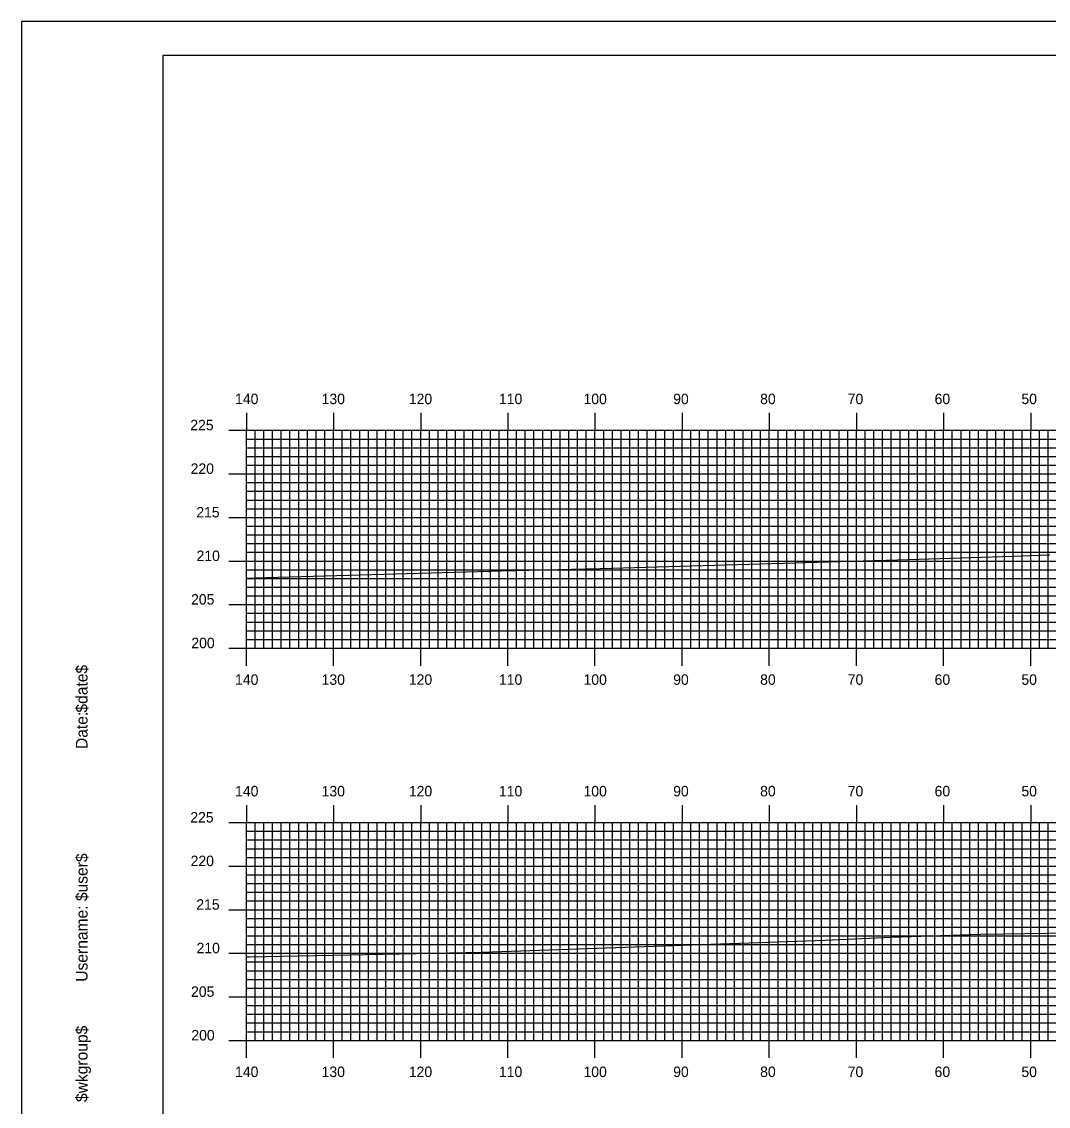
# Model space of a CAD drawing. Extents: x 1821211 to 1821555, y 442591 to 442811.
# Drawn here: x 1821211.4 to 1821329.2, y 442686.1 to 442810.5 of the extents above; entities that cross this region are included whole.
import ezdxf

# ---------------------------------------------------------------- set-up
doc = ezdxf.new("R2010")
doc.units = 0
for name, color, linetype in [('BORDER', 7, 'Continuous'), ('H_V ANNOTATION', 7, 'Continuous'), ('MAJOR', 7, 'Continuous'), ('MINOR', 7, 'Continuous'), ('PLOT BOUNDARY', 7, 'Continuous'), ('S_Roadway_Centerline', 7, 'Continuous')]:
    doc.layers.add(name, color=color, linetype=linetype)

msp = doc.modelspace()

# ---------------------------------------------------------------- linework, layer by layer
at = {"layer": 'BORDER'}
msp.add_lwpolyline([(1821227.63, 442596.67), (1821547.63, 442596.67), (1821547.63, 442806.67), (1821227.63, 442806.67)], close=True, dxfattribs=at)
at = {"layer": 'MAJOR'}
for p, q in [((1821237.23, 442765.67), (1821237.23, 442763.67)), ((1821247.23, 442765.67), (1821247.23, 442763.67)), ((1821257.23, 442765.67), (1821257.23, 442763.67)), ((1821267.23, 442765.67), (1821267.23, 442763.67)), ((1821277.23, 442765.67), (1821277.23, 442763.67)), ((1821287.23, 442765.67), (1821287.23, 442763.67)), ((1821297.23, 442765.67), (1821297.23, 442763.67)), ((1821307.23, 442765.67), (1821307.23, 442763.67)), ((1821317.23, 442765.67), (1821317.23, 442763.67)), ((1821327.23, 442765.67), (1821327.23, 442763.67)), ((1821235.23, 442763.67), (1821237.23, 442763.67)), ((1821237.23, 442763.67), (1821517.23, 442763.67)), ((1821237.23, 442738.67), (1821237.23, 442763.67)), ((1821237.23, 442738.67), (1821237.23, 442763.67)), ((1821237.23, 442763.67), (1821517.23, 442763.67)), ((1821247.23, 442738.67), (1821247.23, 442763.67)), ((1821257.23, 442738.67), (1821257.23, 442763.67)), ((1821267.23, 442738.67), (1821267.23, 442763.67)), ((1821277.23, 442738.67), (1821277.23, 442763.67)), ((1821287.23, 442738.67), (1821287.23, 442763.67)), ((1821297.23, 442738.67), (1821297.23, 442763.67)), ((1821307.23, 442738.67), (1821307.23, 442763.67)), ((1821317.23, 442738.67), (1821317.23, 442763.67)), ((1821327.23, 442738.67), (1821327.23, 442763.67)), ((1821235.23, 442758.67), (1821237.23, 442758.67)), ((1821237.23, 442758.67), (1821517.23, 442758.67)), ((1821235.23, 442753.67), (1821237.23, 442753.67)), ((1821237.23, 442753.67), (1821517.23, 442753.67)), ((1821235.23, 442748.67), (1821237.23, 442748.67)), ((1821237.23, 442748.67), (1821517.23, 442748.67)), ((1821235.23, 442743.67), (1821237.23, 442743.67)), ((1821237.23, 442743.67), (1821517.23, 442743.67)), ((1821235.23, 442738.67), (1821237.23, 442738.67)), ((1821237.23, 442738.67), (1821517.23, 442738.67)), ((1821237.23, 442738.67), (1821517.23, 442738.67)), ((1821237.23, 442736.66), (1821237.23, 442738.67)), ((1821247.23, 442736.66), (1821247.23, 442738.67)), ((1821257.23, 442736.66), (1821257.23, 442738.67)), ((1821267.23, 442736.66), (1821267.23, 442738.67)), ((1821277.23, 442736.66), (1821277.23, 442738.67)), ((1821287.23, 442736.66), (1821287.23, 442738.67)), ((1821297.23, 442736.66), (1821297.23, 442738.67)), ((1821307.23, 442736.66), (1821307.23, 442738.67)), ((1821317.23, 442736.66), (1821317.23, 442738.67)), ((1821327.23, 442736.66), (1821327.23, 442738.67)), ((1821237.23, 442720.67), (1821237.23, 442718.67)), ((1821247.23, 442720.67), (1821247.23, 442718.67)), ((1821257.23, 442720.67), (1821257.23, 442718.67)), ((1821267.23, 442720.67), (1821267.23, 442718.67)), ((1821277.23, 442720.67), (1821277.23, 442718.67)), ((1821287.23, 442720.67), (1821287.23, 442718.67)), ((1821297.23, 442720.67), (1821297.23, 442718.67)), ((1821307.23, 442720.67), (1821307.23, 442718.67)), ((1821317.23, 442720.67), (1821317.23, 442718.67)), ((1821327.23, 442720.67), (1821327.23, 442718.67)), ((1821235.23, 442718.67), (1821237.23, 442718.67)), ((1821237.23, 442718.67), (1821517.23, 442718.67)), ((1821237.23, 442693.67), (1821237.23, 442718.67)), ((1821237.23, 442693.67), (1821237.23, 442718.67)), ((1821237.23, 442718.67), (1821517.23, 442718.67)), ((1821247.23, 442693.67), (1821247.23, 442718.67)), ((1821257.23, 442693.67), (1821257.23, 442718.67)), ((1821267.23, 442693.67), (1821267.23, 442718.67)), ((1821277.23, 442693.67), (1821277.23, 442718.67)), ((1821287.23, 442693.67), (1821287.23, 442718.67)), ((1821297.23, 442693.67), (1821297.23, 442718.67)), ((1821307.23, 442693.67), (1821307.23, 442718.67)), ((1821317.23, 442693.67), (1821317.23, 442718.67)), ((1821327.23, 442693.67), (1821327.23, 442718.67)), ((1821235.23, 442713.67), (1821237.23, 442713.67)), ((1821237.23, 442713.67), (1821517.23, 442713.67)), ((1821235.23, 442708.67), (1821237.23, 442708.67)), ((1821237.23, 442708.67), (1821517.23, 442708.67)), ((1821235.23, 442703.67), (1821237.23, 442703.67)), ((1821237.23, 442703.67), (1821517.23, 442703.67)), ((1821235.23, 442698.67), (1821237.23, 442698.67)), ((1821237.23, 442698.67), (1821517.23, 442698.67)), ((1821235.23, 442693.67), (1821237.23, 442693.67)), ((1821237.23, 442693.67), (1821517.23, 442693.67)), ((1821237.23, 442693.67), (1821517.23, 442693.67)), ((1821237.23, 442691.66), (1821237.23, 442693.67)), ((1821247.23, 442691.66), (1821247.23, 442693.67)), ((1821257.23, 442691.66), (1821257.23, 442693.67)), ((1821267.23, 442691.66), (1821267.23, 442693.67)), ((1821277.23, 442691.66), (1821277.23, 442693.67)), ((1821287.23, 442691.66), (1821287.23, 442693.67)), ((1821297.23, 442691.66), (1821297.23, 442693.67)), ((1821307.23, 442691.66), (1821307.23, 442693.67)), ((1821317.23, 442691.66), (1821317.23, 442693.67)), ((1821327.23, 442691.66), (1821327.23, 442693.67))]:
    msp.add_line(p, q, dxfattribs=at)
at = {"layer": 'MINOR'}
for p, q in [((1821237.23, 442762.67), (1821517.23, 442762.67)), ((1821237.23, 442762.67), (1821239.23, 442762.67)), ((1821238.23, 442738.67), (1821238.23, 442763.67)), ((1821239.23, 442738.67), (1821239.23, 442763.67)), ((1821240.23, 442738.67), (1821240.23, 442763.67)), ((1821241.23, 442738.67), (1821241.23, 442763.67)), ((1821242.23, 442738.67), (1821242.23, 442763.67)), ((1821243.23, 442738.67), (1821243.23, 442763.67)), ((1821244.23, 442738.67), (1821244.23, 442763.67)), ((1821245.23, 442738.67), (1821245.23, 442763.67)), ((1821246.23, 442738.67), (1821246.23, 442763.67)), ((1821248.23, 442738.67), (1821248.23, 442763.67)), ((1821249.23, 442738.67), (1821249.23, 442763.67)), ((1821250.23, 442738.67), (1821250.23, 442763.67)), ((1821251.23, 442738.67), (1821251.23, 442763.67)), ((1821252.23, 442738.67), (1821252.23, 442763.67)), ((1821253.23, 442738.67), (1821253.23, 442763.67)), ((1821254.23, 442738.67), (1821254.23, 442763.67)), ((1821255.23, 442738.67), (1821255.23, 442763.67)), ((1821256.23, 442738.67), (1821256.23, 442763.67)), ((1821258.23, 442738.67), (1821258.23, 442763.67)), ((1821259.23, 442738.67), (1821259.23, 442763.67)), ((1821260.23, 442738.67), (1821260.23, 442763.67)), ((1821261.23, 442738.67), (1821261.23, 442763.67)), ((1821262.23, 442738.67), (1821262.23, 442763.67)), ((1821263.23, 442738.67), (1821263.23, 442763.67)), ((1821264.23, 442738.67), (1821264.23, 442763.67)), ((1821265.23, 442738.67), (1821265.23, 442763.67)), ((1821266.23, 442738.67), (1821266.23, 442763.67)), ((1821268.23, 442738.67), (1821268.23, 442763.67)), ((1821269.23, 442738.67), (1821269.23, 442763.67)), ((1821270.23, 442738.67), (1821270.23, 442763.67)), ((1821271.23, 442738.67), (1821271.23, 442763.67)), ((1821272.23, 442738.67), (1821272.23, 442763.67)), ((1821273.23, 442738.67), (1821273.23, 442763.67)), ((1821274.23, 442738.67), (1821274.23, 442763.67)), ((1821275.23, 442738.67), (1821275.23, 442763.67)), ((1821276.23, 442738.67), (1821276.23, 442763.67)), ((1821278.23, 442738.67), (1821278.23, 442763.67)), ((1821279.23, 442738.67), (1821279.23, 442763.67)), ((1821280.23, 442738.67), (1821280.23, 442763.67)), ((1821281.23, 442738.67), (1821281.23, 442763.67)), ((1821282.23, 442738.67), (1821282.23, 442763.67)), ((1821283.23, 442738.67), (1821283.23, 442763.67)), ((1821284.23, 442738.67), (1821284.23, 442763.67)), ((1821285.23, 442738.67), (1821285.23, 442763.67)), ((1821286.23, 442738.67), (1821286.23, 442763.67)), ((1821288.23, 442738.67), (1821288.23, 442763.67)), ((1821289.23, 442738.67), (1821289.23, 442763.67)), ((1821290.23, 442738.67), (1821290.23, 442763.67)), ((1821291.23, 442738.67), (1821291.23, 442763.67)), ((1821292.23, 442738.67), (1821292.23, 442763.67)), ((1821293.23, 442738.67), (1821293.23, 442763.67)), ((1821294.23, 442738.67), (1821294.23, 442763.67)), ((1821295.23, 442738.67), (1821295.23, 442763.67)), ((1821296.23, 442738.67), (1821296.23, 442763.67)), ((1821298.23, 442738.67), (1821298.23, 442763.67)), ((1821299.23, 442738.67), (1821299.23, 442763.67)), ((1821300.23, 442738.67), (1821300.23, 442763.67)), ((1821301.23, 442738.67), (1821301.23, 442763.67)), ((1821302.23, 442738.67), (1821302.23, 442763.67)), ((1821303.23, 442738.67), (1821303.23, 442763.67)), ((1821304.23, 442738.67), (1821304.23, 442763.67)), ((1821305.23, 442738.67), (1821305.23, 442763.67)), ((1821306.23, 442738.67), (1821306.23, 442763.67)), ((1821308.23, 442738.67), (1821308.23, 442763.67)), ((1821309.23, 442738.67), (1821309.23, 442763.67)), ((1821310.23, 442738.67), (1821310.23, 442763.67)), ((1821311.23, 442738.67), (1821311.23, 442763.67)), ((1821312.23, 442738.67), (1821312.23, 442763.67)), ((1821313.23, 442738.67), (1821313.23, 442763.67)), ((1821314.23, 442738.67), (1821314.23, 442763.67)), ((1821315.23, 442738.67), (1821315.23, 442763.67)), ((1821316.23, 442738.67), (1821316.23, 442763.67)), ((1821318.23, 442738.67), (1821318.23, 442763.67)), ((1821319.23, 442738.67), (1821319.23, 442763.67)), ((1821320.23, 442738.67), (1821320.23, 442763.67)), ((1821321.23, 442738.67), (1821321.23, 442763.67)), ((1821322.23, 442738.67), (1821322.23, 442763.67)), ((1821323.23, 442738.67), (1821323.23, 442763.67)), ((1821324.23, 442738.67), (1821324.23, 442763.67)), ((1821325.23, 442738.67), (1821325.23, 442763.67)), ((1821326.23, 442738.67), (1821326.23, 442763.67)), ((1821328.23, 442738.67), (1821328.23, 442763.67)), ((1821329.23, 442738.67), (1821329.23, 442763.67)), ((1821237.23, 442761.67), (1821517.23, 442761.67)), ((1821237.23, 442761.67), (1821239.23, 442761.67)), ((1821237.23, 442760.67), (1821517.23, 442760.67)), ((1821237.23, 442760.67), (1821239.23, 442760.67)), ((1821237.23, 442759.67), (1821517.23, 442759.67)), ((1821237.23, 442759.67), (1821239.23, 442759.67)), ((1821237.23, 442757.67), (1821517.23, 442757.67)), ((1821237.23, 442757.67), (1821239.23, 442757.67)), ((1821237.23, 442756.67), (1821517.23, 442756.67)), ((1821237.23, 442756.67), (1821239.23, 442756.67)), ((1821237.23, 442755.67), (1821517.23, 442755.67)), ((1821237.23, 442755.67), (1821239.23, 442755.67)), ((1821237.23, 442754.67), (1821517.23, 442754.67)), ((1821237.23, 442754.67), (1821239.23, 442754.67)), ((1821237.23, 442752.67), (1821517.23, 442752.67)), ((1821237.23, 442752.67), (1821239.23, 442752.67)), ((1821237.23, 442751.67), (1821517.23, 442751.67)), ((1821237.23, 442751.67), (1821239.23, 442751.67)), ((1821237.23, 442750.67), (1821517.23, 442750.67)), ((1821237.23, 442750.67), (1821239.23, 442750.67)), ((1821237.23, 442749.67), (1821517.23, 442749.67)), ((1821237.23, 442749.67), (1821239.23, 442749.67)), ((1821237.23, 442747.67), (1821517.23, 442747.67)), ((1821237.23, 442747.67), (1821239.23, 442747.67)), ((1821237.23, 442746.67), (1821517.23, 442746.67)), ((1821237.23, 442746.67), (1821239.23, 442746.67)), ((1821237.23, 442745.67), (1821517.23, 442745.67)), ((1821237.23, 442745.67), (1821239.23, 442745.67)), ((1821237.23, 442744.67), (1821517.23, 442744.67)), ((1821237.23, 442744.67), (1821239.23, 442744.67)), ((1821237.23, 442742.67), (1821517.23, 442742.67)), ((1821237.23, 442742.67), (1821239.23, 442742.67)), ((1821237.23, 442741.67), (1821517.23, 442741.67)), ((1821237.23, 442741.67), (1821239.23, 442741.67)), ((1821237.23, 442740.67), (1821517.23, 442740.67)), ((1821237.23, 442740.67), (1821239.23, 442740.67)), ((1821237.23, 442739.67), (1821517.23, 442739.67)), ((1821237.23, 442739.67), (1821239.23, 442739.67)), ((1821238.23, 442693.67), (1821238.23, 442718.67)), ((1821239.23, 442693.67), (1821239.23, 442718.67)), ((1821240.23, 442693.67), (1821240.23, 442718.67)), ((1821241.23, 442693.67), (1821241.23, 442718.67)), ((1821242.23, 442693.67), (1821242.23, 442718.67)), ((1821243.23, 442693.67), (1821243.23, 442718.67)), ((1821244.23, 442693.67), (1821244.23, 442718.67)), ((1821245.23, 442693.67), (1821245.23, 442718.67)), ((1821246.23, 442693.67), (1821246.23, 442718.67)), ((1821248.23, 442693.67), (1821248.23, 442718.67)), ((1821249.23, 442693.67), (1821249.23, 442718.67)), ((1821250.23, 442693.67), (1821250.23, 442718.67)), ((1821251.23, 442693.67), (1821251.23, 442718.67)), ((1821252.23, 442693.67), (1821252.23, 442718.67)), ((1821253.23, 442693.67), (1821253.23, 442718.67)), ((1821254.23, 442693.67), (1821254.23, 442718.67)), ((1821255.23, 442693.67), (1821255.23, 442718.67)), ((1821256.23, 442693.67), (1821256.23, 442718.67)), ((1821258.23, 442693.67), (1821258.23, 442718.67)), ((1821259.23, 442693.67), (1821259.23, 442718.67)), ((1821260.23, 442693.67), (1821260.23, 442718.67)), ((1821261.23, 442693.67), (1821261.23, 442718.67)), ((1821262.23, 442693.67), (1821262.23, 442718.67)), ((1821263.23, 442693.67), (1821263.23, 442718.67)), ((1821264.23, 442693.67), (1821264.23, 442718.67)), ((1821265.23, 442693.67), (1821265.23, 442718.67)), ((1821266.23, 442693.67), (1821266.23, 442718.67)), ((1821268.23, 442693.67), (1821268.23, 442718.67)), ((1821269.23, 442693.67), (1821269.23, 442718.67)), ((1821270.23, 442693.67), (1821270.23, 442718.67)), ((1821271.23, 442693.67), (1821271.23, 442718.67)), ((1821272.23, 442693.67), (1821272.23, 442718.67)), ((1821273.23, 442693.67), (1821273.23, 442718.67)), ((1821274.23, 442693.67), (1821274.23, 442718.67)), ((1821275.23, 442693.67), (1821275.23, 442718.67)), ((1821276.23, 442693.67), (1821276.23, 442718.67)), ((1821278.23, 442693.67), (1821278.23, 442718.67)), ((1821279.23, 442693.67), (1821279.23, 442718.67)), ((1821280.23, 442693.67), (1821280.23, 442718.67)), ((1821281.23, 442693.67), (1821281.23, 442718.67)), ((1821282.23, 442693.67), (1821282.23, 442718.67)), ((1821283.23, 442693.67), (1821283.23, 442718.67)), ((1821284.23, 442693.67), (1821284.23, 442718.67)), ((1821285.23, 442693.67), (1821285.23, 442718.67)), ((1821286.23, 442693.67), (1821286.23, 442718.67)), ((1821288.23, 442693.67), (1821288.23, 442718.67)), ((1821289.23, 442693.67), (1821289.23, 442718.67)), ((1821290.23, 442693.67), (1821290.23, 442718.67)), ((1821291.23, 442693.67), (1821291.23, 442718.67)), ((1821292.23, 442693.67), (1821292.23, 442718.67)), ((1821293.23, 442693.67), (1821293.23, 442718.67)), ((1821294.23, 442693.67), (1821294.23, 442718.67)), ((1821295.23, 442693.67), (1821295.23, 442718.67)), ((1821296.23, 442693.67), (1821296.23, 442718.67)), ((1821298.23, 442693.67), (1821298.23, 442718.67)), ((1821299.23, 442693.67), (1821299.23, 442718.67)), ((1821300.23, 442693.67), (1821300.23, 442718.67)), ((1821301.23, 442693.67), (1821301.23, 442718.67)), ((1821302.23, 442693.67), (1821302.23, 442718.67)), ((1821303.23, 442693.67), (1821303.23, 442718.67)), ((1821304.23, 442693.67), (1821304.23, 442718.67)), ((1821305.23, 442693.67), (1821305.23, 442718.67)), ((1821306.23, 442693.67), (1821306.23, 442718.67)), ((1821308.23, 442693.67), (1821308.23, 442718.67)), ((1821309.23, 442693.67), (1821309.23, 442718.67)), ((1821310.23, 442693.67), (1821310.23, 442718.67)), ((1821311.23, 442693.67), (1821311.23, 442718.67)), ((1821312.23, 442693.67), (1821312.23, 442718.67)), ((1821313.23, 442693.67), (1821313.23, 442718.67)), ((1821314.23, 442693.67), (1821314.23, 442718.67)), ((1821315.23, 442693.67), (1821315.23, 442718.67)), ((1821316.23, 442693.67), (1821316.23, 442718.67)), ((1821318.23, 442693.67), (1821318.23, 442718.67)), ((1821319.23, 442693.67), (1821319.23, 442718.67)), ((1821320.23, 442693.67), (1821320.23, 442718.67)), ((1821321.23, 442693.67), (1821321.23, 442718.67)), ((1821322.23, 442693.67), (1821322.23, 442718.67)), ((1821323.23, 442693.67), (1821323.23, 442718.67)), ((1821324.23, 442693.67), (1821324.23, 442718.67)), ((1821325.23, 442693.67), (1821325.23, 442718.67)), ((1821326.23, 442693.67), (1821326.23, 442718.67)), ((1821328.23, 442693.67), (1821328.23, 442718.67)), ((1821329.23, 442693.67), (1821329.23, 442718.67)), ((1821237.23, 442717.67), (1821517.23, 442717.67)), ((1821237.23, 442717.67), (1821239.23, 442717.67)), ((1821237.23, 442716.67), (1821517.23, 442716.67)), ((1821237.23, 442716.67), (1821239.23, 442716.67)), ((1821237.23, 442715.67), (1821517.23, 442715.67)), ((1821237.23, 442715.67), (1821239.23, 442715.67)), ((1821237.23, 442714.67), (1821517.23, 442714.67)), ((1821237.23, 442714.67), (1821239.23, 442714.67)), ((1821237.23, 442712.67), (1821517.23, 442712.67)), ((1821237.23, 442712.67), (1821239.23, 442712.67)), ((1821237.23, 442711.67), (1821517.23, 442711.67)), ((1821237.23, 442711.67), (1821239.23, 442711.67)), ((1821237.23, 442710.67), (1821517.23, 442710.67)), ((1821237.23, 442710.67), (1821239.23, 442710.67)), ((1821237.23, 442709.67), (1821517.23, 442709.67)), ((1821237.23, 442709.67), (1821239.23, 442709.67)), ((1821237.23, 442707.67), (1821517.23, 442707.67)), ((1821237.23, 442707.67), (1821239.23, 442707.67)), ((1821237.23, 442706.67), (1821517.23, 442706.67)), ((1821237.23, 442706.67), (1821239.23, 442706.67)), ((1821237.23, 442705.67), (1821517.23, 442705.67)), ((1821237.23, 442705.67), (1821239.23, 442705.67)), ((1821237.23, 442704.67), (1821517.23, 442704.67)), ((1821237.23, 442704.67), (1821239.23, 442704.67)), ((1821237.23, 442702.67), (1821517.23, 442702.67)), ((1821237.23, 442702.67), (1821239.23, 442702.67)), ((1821237.23, 442701.67), (1821517.23, 442701.67)), ((1821237.23, 442701.67), (1821239.23, 442701.67)), ((1821237.23, 442700.67), (1821517.23, 442700.67)), ((1821237.23, 442700.67), (1821239.23, 442700.67)), ((1821237.23, 442699.67), (1821517.23, 442699.67)), ((1821237.23, 442699.67), (1821239.23, 442699.67)), ((1821237.23, 442697.67), (1821517.23, 442697.67)), ((1821237.23, 442697.67), (1821239.23, 442697.67)), ((1821237.23, 442696.67), (1821517.23, 442696.67)), ((1821237.23, 442696.67), (1821239.23, 442696.67)), ((1821237.23, 442695.67), (1821517.23, 442695.67)), ((1821237.23, 442695.67), (1821239.23, 442695.67)), ((1821237.23, 442694.67), (1821517.23, 442694.67)), ((1821237.23, 442694.67), (1821239.23, 442694.67))]:
    msp.add_line(p, q, dxfattribs=at)
at = {"layer": 'PLOT BOUNDARY'}
msp.add_lwpolyline([(1821211.44, 442590.55), (1821551.44, 442590.55), (1821551.44, 442810.55), (1821211.44, 442810.55)], close=True, dxfattribs=at)
at = {"layer": 'S_Roadway_Centerline'}
for points in [[(1821237.23, 442746.71), (1821238.14, 442746.75), (1821266.46, 442747.53), (1821274.53, 442747.74), (1821277.82, 442747.81), (1821313.25, 442748.83), (1821325.17, 442749.23), (1821329.44, 442749.38)], [(1821237.23, 442703.27), (1821237.53, 442703.28), (1821264.33, 442703.79), (1821303.65, 442705.19), (1821311.23, 442705.53), (1821321.49, 442705.86), (1821351.91, 442706.32), (1821353.94, 442706.35), (1821354.59, 442706.37), (1821355.88, 442706.42), (1821388.83, 442707.87), (1821420.29, 442709.25), (1821422.31, 442709.32), (1821426.24, 442709.4), (1821439.35, 442709.51), (1821465.23, 442709.52), (1821471.24, 442709.51), (1821476.19, 442709.63), (1821481.91, 442709.95), (1821490.45, 442710.34), (1821494.15, 442710.38), (1821514.65, 442710.89), (1821517.23, 442710.91)]]:
    msp.add_lwpolyline(points, dxfattribs=at)

# ---------------------------------------------------------------- texts
at = {"layer": 'BORDER'}
for s, p in [('$date$', (1821219, 442731.28)), ('Date:', (1821219, 442727.1)), ('$user$', (1821219, 442709.65)), ('Username:', (1821219, 442700.4)), ('$wkgroup$', (1821219, 442686.6))]:
    msp.add_text(s, height=1.339, rotation=90, dxfattribs=at).set_placement(p)
at = {"layer": 'H_V ANNOTATION'}
for s, p in [('140', (1821235.93, 442766.67)), ('130', (1821245.86, 442766.67)), ('120', (1821255.87, 442766.67)), ('110', (1821266.21, 442766.67)), ('100', (1821275.91, 442766.67)), ('90', (1821286.2, 442766.67)), ('80', (1821296.18, 442766.67)), ('70', (1821306.23, 442766.67)), ('60', (1821316.2, 442766.67)), ('50', (1821326.16, 442766.67)), ('225', (1821230.79, 442763.67)), ('220', (1821230.83, 442758.67)), ('215', (1821231.48, 442753.67)), ('210', (1821231.51, 442748.67)), ('205', (1821230.88, 442743.67)), ('200', (1821230.91, 442738.67)), ('140', (1821235.93, 442734.47)), ('130', (1821245.86, 442734.47)), ('120', (1821255.87, 442734.47)), ('110', (1821266.21, 442734.47)), ('100', (1821275.91, 442734.47)), ('90', (1821286.2, 442734.47)), ('80', (1821296.18, 442734.47)), ('70', (1821306.23, 442734.47)), ('60', (1821316.2, 442734.47)), ('50', (1821326.16, 442734.47)), ('140', (1821235.93, 442721.67)), ('130', (1821245.86, 442721.67)), ('120', (1821255.87, 442721.67)), ('110', (1821266.21, 442721.67)), ('100', (1821275.91, 442721.67)), ('90', (1821286.2, 442721.67)), ('80', (1821296.18, 442721.67)), ('70', (1821306.23, 442721.67)), ('60', (1821316.2, 442721.67)), ('50', (1821326.16, 442721.67)), ('225', (1821230.79, 442718.67)), ('220', (1821230.83, 442713.67)), ('215', (1821231.48, 442708.67)), ('210', (1821231.51, 442703.67)), ('205', (1821230.88, 442698.67)), ('200', (1821230.91, 442693.67)), ('140', (1821235.93, 442689.47)), ('130', (1821245.86, 442689.47)), ('120', (1821255.87, 442689.47)), ('110', (1821266.21, 442689.47)), ('100', (1821275.91, 442689.47)), ('90', (1821286.2, 442689.47)), ('80', (1821296.18, 442689.47)), ('70', (1821306.23, 442689.47)), ('60', (1821316.2, 442689.47)), ('50', (1821326.16, 442689.47))]:
    msp.add_text(s, height=1.2, dxfattribs=at).set_placement(p)
at = {"layer": 'MAJOR'}
for p in [(1821237.22, 442738.67), (1821237.22, 442693.67)]:
    msp.add_text('-', height=0.012, dxfattribs=at).set_placement(p)

doc.saveas('drawing.dxf')
